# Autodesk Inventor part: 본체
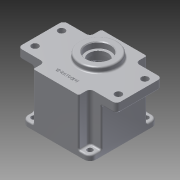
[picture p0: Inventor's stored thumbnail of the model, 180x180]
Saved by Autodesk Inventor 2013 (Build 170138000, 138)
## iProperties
Created: 2015-07
Part Number: 본체
Material: 알루미늄 6061
Document SubType Name: 판금
Designer: user
Density: 2.71 g/cm^3
Sheet Metal Rule: 기본값
Author: user
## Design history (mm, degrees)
sketch "스케치1"
  geometry: L1 (-45, 45)-(45, 45); L2 (45, 45)-(45, -45); L3 (45, -45)-(-45, -45); L4 (-45, -45)-(-45, 45); L5 (-45, 45)-(45, -45); L6 (45, 45)-(-45, -45); 1 further point
  constraints: 12 end point, 2 midpoint, 2 parallel, 1 horizontal, 1 perpendicular
  dimensions: "d0" = 90 distance of L2.end L3.end; "d1" = 90 distance of L1.end L2.end
extrude "돌출1" new body sketch "스케치1" distance "d2" = 70; taper "d3" = 0 deg
sketch "스케치2"
  geometry: L1 (45, -45)-(45, 45) reference; L2 (0, 0)-(0, 11); C1 r 25 at (0, 11)
  constraints: 2 end point, 1 centre point, 1 coincident, 1 parallel
  dimensions: "d4" = 11 distance of L2.start L2.end; "d5" = 50 diameter of C1
extrude "돌출2" join sketch "스케치2" distance "d6" = 7; taper "d7" = 0 deg
sketch "스케치3"
  geometry: C1 r 40 at (0, 0); 1 further point
  constraints: 1 centre point, 1 coincident
  dimensions: "d8" = 80 diameter of C1
extrude "돌출3" cut sketch "스케치3" distance "d9" = 9; taper "d10" = 0 deg
sketch "스케치4"
  geometry: L1 (65, -30)-(-65, -30); L2 (-65, -30)-(-65, 30); L3 (-65, 30)-(65, 30); L4 (65, 30)-(65, -30); L5 (65, -30)-(-65, 30); L6 (-65, -30)-(65, 30); 1 further point
  constraints: 12 end point, 2 midpoint, 2 parallel, 1 horizontal, 1 perpendicular
  dimensions: "d11" = 130 distance of L2.end L3.end; "d12" = 60 distance of L1.end L2.end
extrude "돌출4" join sketch "스케치4" distance "d13" = 12; taper "d14" = 0 deg
sketch "스케치5"
  geometry: L1 (-45, 45)-(-30, 45); L2 (-30, 45)-(-30, 30); L3 (-30, 30)-(-45, 30); L4 (-45, 30)-(-45, 45); 1 further point
  constraints: 8 end point, 2 parallel, 1 horizontal, 1 perpendicular
  dimensions: "d15" = 15 distance of L2.end L3.end; "d16" = 15 distance of L1.end L2.end
extrude "돌출5" cut sketch "스케치5" distance "d17" = 63; taper "d18" = 0 deg
fillet "모깎기1" dims "d22" = 5
fillet "모깎기2" dims "d23" = 8
sketch "스케치6"
  geometry: C1 r 40 at (0, 0) reference; C2 r 39 at (0, 0)
  constraints: 1 centre point, 1 coincident
  dimensions: "d24" = 78 diameter of C2
extrude "돌출6" cut sketch "스케치6" distance "d25" = 52; taper "d26" = 0 deg
fillet "모깎기3" dims "d27" = 2
fillet "모깎기4" dims "d28" = 2
sketch "스케치7"
  geometry: L1 (0, 0)-(0, 11); L2 (0, 0)-(0, -20); C1 r 39 at (0, 0) reference; A1 r 20.5 centre (0, 11) between (7.402, -8.117) and (-7.402, -8.117); A2 r 14 centre (0, -20) between (-7.402, -8.117) and (7.402, -8.117)
  constraints: 4 end point, 4 point on circle, 2 centre point, 2 coincident, 1 collinear, 1 vertical
  dimensions: "d29" = 11 distance of L1.start L1.end; "d30" = 41 diameter of A1; "d31" = 20 distance of L1.start L2.end; "d32" = 28 diameter of A2
extrude "돌출7" join sketch "스케치7" distance "d33" = 7; taper "d34" = 0 deg
fillet "모깎기5" dims "d35" = 3
fillet "모깎기6" dims "d36" = 2
sketch "스케치8"
  geometry: C1 r 17.5 at (0, 11); A1 r 18.5 centre (0, 11) between (10.031, -4.545) and (-10.031, -4.545) reference; 1 further point
  constraints: 1 centre point, 1 coincident
  dimensions: "d37" = 35 diameter of C1
extrude "돌출8" cut sketch "스케치8" distance "d38" = 10; taper "d39" = 0 deg
sketch "스케치9"
  geometry: C1 r 17.5 at (0, 0) reference; C2 r 12.5 at (0, 0); 1 further point
  constraints: 1 centre point, 1 coincident
  dimensions: "d40" = 25 diameter of C2
extrude "돌출9" cut sketch "스케치9" distance "d41" = 5; taper "d42" = 0 deg
sketch "스케치12"
  geometry: C1 r 25 at (0, 0) reference; C2 r 16 at (0, 0); 1 further point
  constraints: 1 centre point, 1 coincident
  dimensions: "d46" = 32 diameter of C2
extrude "돌출11" cut sketch "스케치12" distance "d47" = 8; taper "d48" = 0 deg
sketch "스케치13"
  geometry: C1 r 11 at (0, -20); A1 r 12 centre (0, -20) between (-8.994, -12.056) and (8.994, -12.056) reference; 1 further point
  constraints: 1 centre point, 1 coincident
  dimensions: "d49" = 22 diameter of C1
extrude "돌출12" cut sketch "스케치13" distance "d50" = 7; taper "d51" = 0 deg
sketch "스케치14"
  geometry: C1 r 11 at (0, 0) reference; C2 r 9.5 at (0, 0); 1 further point
  constraints: 1 centre point, 1 coincident
  dimensions: "d52" = 19 diameter of C2
extrude "돌출13" cut sketch "스케치14" distance "d53" = 1; taper "d54" = 0 deg
fillet "모깎기7" dims "d55" = 2
fillet "모깎기8" dims "d56" = 0.3
chamfer "모따기1" distance "d57" = 1; stored, may be unused: second distance "d58" = 2, angle "d59" = 45 deg
fillet "모깎기9" dims "d60" = 2
sketch "스케치15"
  geometry: L1 (-24.749, -24.749)-(24.749, 24.749); A1 r 4 centre (-24.749, 24.749) between (-27.462, 21.809) and (-21.809, 27.462); A2 r 4 centre (24.749, 24.749) between (21.809, 27.462) and (27.462, 21.809); A3 r 4 centre (24.749, -24.749) between (27.462, -21.809) and (21.809, -27.462); A4 r 4 centre (-24.749, -24.749) between (-21.809, -27.462) and (-27.462, -21.809); A5 r 3.5 centre (-19.238, 29.836) between (-21.134, 32.777) and (-21.762, 27.412); A6 r 3.5 centre (-29.836, 19.238) between (-27.412, 21.762) and (-32.777, 21.134); A7 r 3.5 centre (19.238, 29.836) between (21.762, 27.412) and (21.134, 32.777); A8 r 3.5 centre (29.836, 19.238) between (32.777, 21.134) and (27.412, 21.762); A9 r 3.5 centre (-19.238, -29.836) between (-21.762, -27.412) and (-21.134, -32.777); A10 r 3.5 centre (-29.836, -19.238) between (-32.777, -21.134) and (-27.412, -21.762); A11 r 3.5 centre (19.238, -29.836) between (21.134, -32.777) and (21.762, -27.412); A12 r 3.5 centre (29.836, -19.238) between (27.412, -21.762) and (32.777, -21.134); A13 r 39 centre (0, 0) between (21.134, -32.777) and (32.777, -21.134); A14 r 39 centre (0, 0) between (-32.777, -21.134) and (-21.134, -32.777); A15 r 39 centre (0, 0) between (32.777, 21.134) and (21.134, 32.777); A16 r 39 centre (0, 0) between (-21.134, 32.777) and (-32.777, 21.134)
  constraints: 40 point on circle, 16 centre point, 2 coincident, 2 end point, 1 midpoint, 1 tangent
  dimensions: "d63" = 8 diameter of A1; "d64" = 8 diameter of A2; "d66" = 8 diameter of A4; "d67" = 7 diameter of A5; "d68" = 4 radius of A3
extrude "돌출14" join sketch "스케치15" distance "d69" = 52; taper "d70" = 0 deg
fillet "모깎기10" dims "d71" = 2
sketch "스케치16"
  geometry: C1 r 2 at (-24.749, 24.749); A1 r 4 centre (-24.749, 24.749) between (-27.462, 21.809) and (-21.809, 27.462) reference
  constraints: 1 centre point, 1 coincident
  dimensions: "d72" = 4 diameter of C1
hole "구멍1" sketch "스케치16" at (-24.749, 24.749) diameter "d73" = 3.459; stored, may be unused: countersink angle "d77" = 90 deg, drill point angle "d79" = 118 deg; dims "d74" = 12, "d75" = 4, "d76" = 2, "d78" = 15
sketch "스케치17"
  geometry: L1 (55, -17.5)-(-55, -17.5); L2 (-55, -17.5)-(-55, 17.5); L3 (-55, 17.5)-(55, 17.5); L4 (55, 17.5)-(55, -17.5); L5 (55, -17.5)-(-55, 17.5); L6 (-55, -17.5)-(55, 17.5); C1 r 4.5 at (-55, 17.5); C2 r 4.5 at (-55, -17.5); C3 r 4.5 at (55, -17.5); C4 r 4.5 at (55, 17.5); 1 further point
  constraints: 12 end point, 4 centre point, 4 coincident, 2 midpoint, 2 parallel, 1 horizontal, 1 perpendicular
  dimensions: "d83" = 110 distance of L2.end L3.end; "d84" = 35 distance of L1.end L2.end; "d85" = 9 diameter of C1; "d86" = 9 diameter of C2; "d87" = 9 diameter of C3; "d88" = 9 diameter of C4
extrude "돌출15" cut sketch "스케치17" distance "d89" = 52; taper "d90" = 0 deg
sketch "스케치18"
  geometry: C1 r 3.5 at (-37, 37); C2 r 3.5 at (37, 37); C3 r 3.5 at (37, -37); C4 r 3.5 at (-37, -37); A1 r 8 centre (37, -37) between (37, -45) and (45, -37) reference; A2 r 8 centre (37, 37) between (45, 37) and (37, 45) reference; A3 r 8 centre (-37, 37) between (-37, 45) and (-45, 37) reference; A4 r 8 centre (-37, -37) between (-45, -37) and (-37, -45) reference
  constraints: 4 centre point, 4 coincident
  dimensions: "d91" = 7 diameter of C1; "d92" = 7 diameter of C2; "d93" = 7 diameter of C3; "d94" = 7 diameter of C4
extrude "돌출16" cut sketch "스케치18" distance "d95" = 52; taper "d96" = 0 deg
sketch "스케치19"
  geometry: L1 (-28, -45)-(28, -45) reference; L2 (-15, -25)-(15, -25); L3 (15, -25)-(15, -35); L4 (15, -35)-(-15, -35); L5 (-15, -35)-(-15, -25); C1 r 27 at (0, 11) reference; 1 further point
  constraints: 2 other
  dimensions: "d97" = 10 distance of L2.end L3.end; "d99" = 10 distance between parallel lines of L1 L4; "d100" = 30 distance of L3.end L4.end; "d101" = 15 distance from line of L3 C1.centre
feature "엠보싱1" sketch "스케치19" dims "d102" = 0.5, "d103" = 0
node "솔리드1"
pattern_circular "원형 패턴1" dims angle "d20" = 360 deg
pattern_circular "원형 패턴2" dims angle "d81" = 360 deg
other parameters: "K계수" = 4.4, "BendRadius" = 3.048 (derived), "BendReliefWidth" = 3.048 (derived), "BendReliefDepth" = 1.524 (derived), "CornerReliefSize" = 12.192 (derived), "SeamGap" = 0.01, "MinimumRemnant" = 6.096 (derived), "TransitionRadius" = 3.048 (= BendRadius)
